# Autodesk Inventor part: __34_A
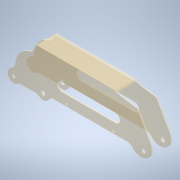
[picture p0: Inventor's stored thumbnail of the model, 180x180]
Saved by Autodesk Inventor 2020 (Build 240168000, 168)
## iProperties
Created: 2017-09
Part Number: __34_A
Material: Bronze, étain doux
Document SubType Name: Modeling
Designer: bruno
Density: 8.874 g/cm^3
Appearance: Huile
Mass: 194.649 g
Surface Area: 235.258 cm^2
Volume: 21.9348 cm^3
Sending System: SolidWorks 2016
Last Author: Prof
Last Saved: 2018-10-03
Author: bruno
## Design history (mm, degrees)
feature "Enlèv. mat.-Extru.1"
sketch "Esquisse1"
  geometry: L1 (202.436, -47.047)-(-106.035, -47.047); L2 (-106.035, -47.047)-(-106.035, -15); L3 (-106.035, -15)-(202.436, -15); L4 (202.436, -15)-(202.436, -47.047); 1 further point
  constraints: 8 end point, 2 parallel, 1 horizontal, 1 perpendicular
extrude "Extrusion1" cut sketch "Esquisse1" distance "d0" = 100; taper "d1" = 0 deg
node "Solide1"
